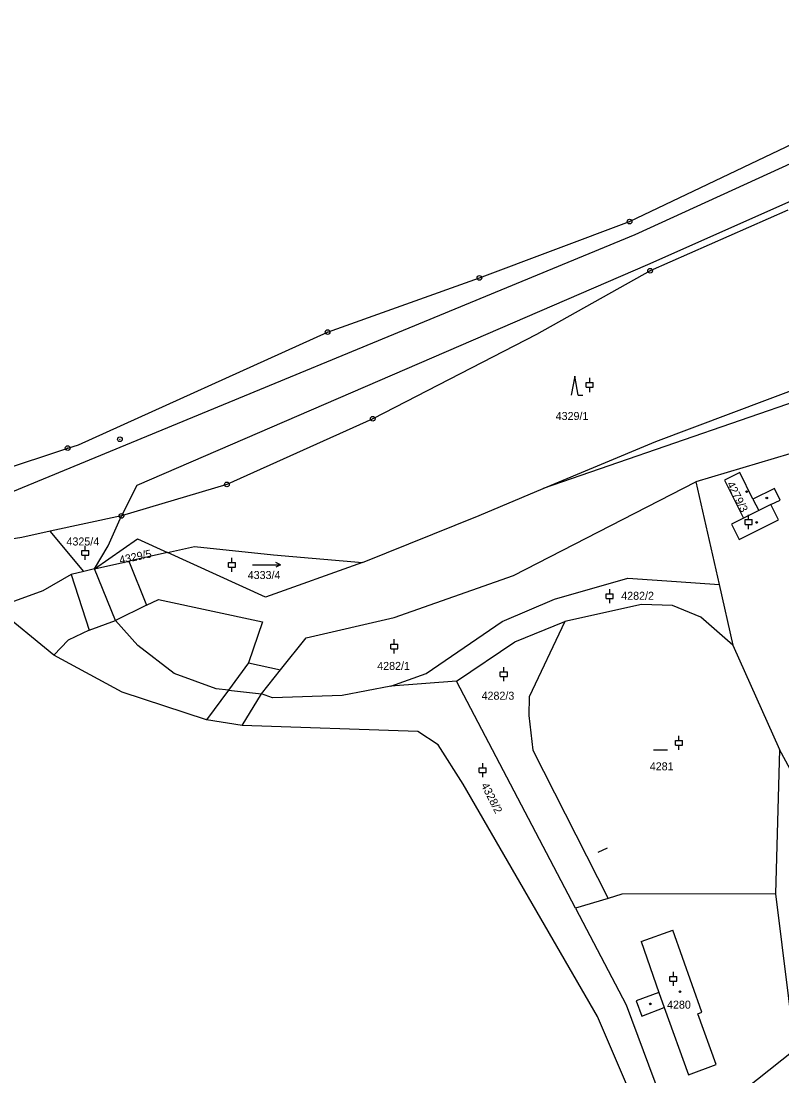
# Model space of a CAD drawing. Extents: x -733394 to -722299, y -1082822 to -1075049.
# Drawn here: x -730959.3 to -730797.5, y -1079150.5 to -1078926.3 of the extents above; entities that cross this region are included whole.
import ezdxf

# ---------------------------------------------------------------- set-up
doc = ezdxf.new("R2010")
doc.units = 0
for name, color, linetype in [('Hranice parcel', 7, 'Continuous'), ('Parcelní čísla', 7, 'Continuous'), ('Vnitřní kresba', 7, 'Continuous'), ('Značky bodu BP', 7, 'Continuous'), ('Značky budov', 7, 'Continuous'), ('Značky kultur', 7, 'Continuous')]:
    doc.layers.add(name, color=color, linetype=linetype)

msp = doc.modelspace()

# ---------------------------------------------------------------- linework, layer by layer
at = {"layer": 'Hranice parcel'}
for p, q in [((-730758.21, -1078994.58), (-730848.25, -1079025.68)), ((-730815.79, -1079024.26), (-730810.86, -1079046.05)), ((-730937.95, -1079031.48), (-730953.08, -1079034.76)), ((-730945.93, -1079043.27), (-730953.08, -1079034.76)), ((-730928.15, -1079039.25), (-730936.34, -1079041.08)), ((-730943.66, -1079042.71), (-730945.93, -1079043.27)), ((-730943.66, -1079042.71), (-730936.34, -1079041.08)), ((-730810.86, -1079046.05), (-730807.95, -1079058.94)), ((-730807.95, -1079058.94), (-730798.03, -1079081.14)), ((-730866.69, -1079066.63), (-730880.7, -1079067.69)), ((-730841.4, -1079114.86), (-730866.69, -1079066.63)), ((-730798.03, -1079081.14), (-730798.88, -1079111.76)), ((-730798.88, -1079111.76), (-730794.74, -1079144.85)), ((-730834.45, -1079112.77), (-730841.4, -1079114.86)), ((-730819.09, -1079164.08), (-730794.74, -1079144.85))]:
    msp.add_line(p, q, dxfattribs=at)
for points in [[(-730987.01, -1079028.33), (-730979.13, -1079026.93), (-730949.37, -1079017.07), (-730947.09, -1079016.4), (-730894.11, -1078992.42), (-730861.84, -1078980.93), (-730829.91, -1078968.95), (-730789, -1078949.44), (-730744.72, -1078928.85), (-730735.03, -1078923.85), (-730722.89, -1078918.38), (-730707.51, -1078912.04)], [(-730796.25, -1078966.53), (-730825.54, -1078979.41), (-730849.68, -1078992.93), (-730884.52, -1079010.85), (-730915.53, -1079024.81), (-730937.95, -1079031.48)], [(-730848.25, -1079025.68), (-730824.32, -1079015.66), (-730792.29, -1079003.64), (-730777.35, -1078991.66), (-730760.34, -1078992.61)], [(-730742.62, -1079005.63), (-730749.62, -1079008.52), (-730753.16, -1079010), (-730767.99, -1079015.09), (-730778.09, -1079014.53), (-730792.49, -1079017.27), (-730815.79, -1079024.26)], [(-730803.73, -1079027.96), (-730806.45, -1079022.27), (-730809.71, -1079023.9), (-730805.68, -1079031.96), (-730808.23, -1079033.23), (-730806.6, -1079036.49), (-730798.25, -1079032.32), (-730799.89, -1079029.03), (-730797.88, -1079028.14), (-730799.12, -1079025.66), (-730803.73, -1079027.96)], [(-730904.1, -1079064.2), (-730898.65, -1079057.37), (-730879.99, -1079053.06), (-730854.58, -1079044.14), (-730815.79, -1079024.26)], [(-730886.71, -1079041.4), (-730861.92, -1079031.4), (-730848.25, -1079025.68)], [(-730943.66, -1079042.71), (-730940.77, -1079037.83), (-730937.95, -1079031.48)], [(-730953.08, -1079034.76), (-730959.14, -1079036.07), (-730969.03, -1079037.66), (-730984.36, -1079040.08), (-730988.05, -1079040.44)], [(-730943.66, -1079042.71), (-730934.49, -1079036.36), (-730928.15, -1079039.25)], [(-730928.15, -1079039.25), (-730922.38, -1079037.96), (-730905.62, -1079039.79), (-730886.71, -1079041.4)], [(-730886.71, -1079041.4), (-730907.29, -1079048.74), (-730928.15, -1079039.25)], [(-730936.34, -1079041.08), (-730932.64, -1079050.47), (-730930.08, -1079049.25), (-730907.92, -1079054.02), (-730910.92, -1079062.73), (-730904.1, -1079064.2)], [(-730945.93, -1079043.27), (-730948.61, -1079043.94), (-730954.65, -1079047.43), (-730964.65, -1079051.01)], [(-730880.7, -1079067.69), (-730873.12, -1079064.97), (-730857.02, -1079053.92), (-730845.88, -1079049.15), (-730830.25, -1079044.72), (-730819.93, -1079045.43), (-730810.86, -1079046.05)], [(-730818.01, -1079184.84), (-730818.76, -1079179.82), (-730836.76, -1079137.87), (-730865.26, -1079088.5), (-730870.59, -1079080.16), (-730874.93, -1079077.28), (-730912.27, -1079075.99), (-730919.86, -1079074.78), (-730937.75, -1079068.97), (-730952.33, -1079061.05), (-730964.65, -1079051.01)], [(-730807.95, -1079058.94), (-730814.74, -1079053.02), (-730820.76, -1079050.51), (-730827.4, -1079050.33), (-730843.65, -1079053.92)], [(-730780.05, -1079050.39), (-730772.67, -1079061.9), (-730784.5, -1079069.05), (-730780.3, -1079075.98), (-730788.63, -1079081.1), (-730790.35, -1079082.13), (-730791.27, -1079080.58), (-730791.98, -1079081), (-730792.65, -1079079.88), (-730794.92, -1079081.23), (-730794.25, -1079082.35), (-730794.94, -1079082.76), (-730794.02, -1079084.31), (-730795.73, -1079085.33), (-730798.03, -1079081.14)], [(-730866.69, -1079066.63), (-730854.32, -1079058.25), (-730843.65, -1079053.92)], [(-730843.65, -1079053.92), (-730851.25, -1079069.96), (-730851.31, -1079073.93), (-730850.45, -1079081.26), (-730834.45, -1079112.77)], [(-730880.7, -1079067.69), (-730891.01, -1079069.66), (-730905.82, -1079070.12), (-730908.16, -1079069.29), (-730904.1, -1079064.2)], [(-730798.88, -1079111.76), (-730831.53, -1079111.89), (-730834.45, -1079112.77)], [(-730841.4, -1079114.86), (-730830.66, -1079135.35), (-730823.42, -1079154.78), (-730819.09, -1079164.08)]]:
    msp.add_lwpolyline(points, dxfattribs=at)
at = {"layer": 'Vnitřní kresba'}
for p, q in [((-730828.75, -1078971.72), (-730789.28, -1078953.63)), ((-730784.77, -1078959.77), (-730826.08, -1078978.11)), ((-730968.57, -1079029.42), (-730828.75, -1078971.72)), ((-730826.08, -1078978.11), (-730934.66, -1079025)), ((-730934.66, -1079025), (-730937.95, -1079031.48)), ((-730803.73, -1079027.96), (-730802.42, -1079030.33)), ((-730799.89, -1079029.03), (-730802.42, -1079030.33)), ((-730802.42, -1079030.33), (-730805.68, -1079031.96)), ((-730939.2, -1079053.7), (-730943.66, -1079042.71)), ((-730948.61, -1079043.94), (-730944.77, -1079055.78)), ((-730932.64, -1079050.47), (-730939.2, -1079053.7)), ((-730944.77, -1079055.78), (-730939.2, -1079053.7)), ((-730934.46, -1079059.02), (-730939.2, -1079053.7)), ((-730944.77, -1079055.78), (-730949.24, -1079057.87)), ((-730949.24, -1079057.87), (-730952.33, -1079061.05)), ((-730926.7, -1079064.98), (-730934.46, -1079059.02)), ((-730910.92, -1079062.73), (-730915.21, -1079068.52)), ((-730917.83, -1079068.23), (-730926.7, -1079064.98)), ((-730915.21, -1079068.52), (-730919.86, -1079074.78)), ((-730915.21, -1079068.52), (-730917.83, -1079068.23)), ((-730915.21, -1079068.52), (-730908.16, -1079069.29)), ((-730912.27, -1079075.99), (-730908.16, -1079069.29)), ((-730836.55, -1079102.96), (-730834.6, -1079102.03)), ((-730827.47, -1079121.93), (-730820.7, -1079119.53)), ((-730814.56, -1079136.94), (-730820.7, -1079119.53)), ((-730827.47, -1079121.93), (-730823.72, -1079132.72)), ((-730823.72, -1079132.72), (-730828.48, -1079134.52)), ((-730828.48, -1079134.52), (-730827.27, -1079137.76)), ((-730823.72, -1079132.72), (-730822.54, -1079135.94)), ((-730827.27, -1079137.76), (-730822.54, -1079135.94)), ((-730822.54, -1079135.94), (-730817.4, -1079150.21)), ((-730815.4, -1079137.26), (-730814.56, -1079136.94)), ((-730811.53, -1079148.06), (-730815.4, -1079137.26)), ((-730817.4, -1079150.21), (-730811.53, -1079148.06))]:
    msp.add_line(p, q, dxfattribs=at)
at = {"layer": 'Značky bodu BP'}
for centre, radius in [((-730829.91, -1078968.95), 0.5), ((-730829.91, -1078968.95), 0.0303), ((-730825.54, -1078979.41), 0.5), ((-730825.54, -1078979.41), 0.0303), ((-730861.84, -1078980.93), 0.5), ((-730861.84, -1078980.93), 0.0303), ((-730894.11, -1078992.42), 0.5), ((-730894.11, -1078992.42), 0.0303), ((-730884.52, -1079010.85), 0.5), ((-730884.52, -1079010.85), 0.0303), ((-730938.27, -1079015.21), 0.5), ((-730938.27, -1079015.21), 0.0303), ((-730949.37, -1079017.07), 0.5), ((-730949.37, -1079017.07), 0.0303), ((-730915.53, -1079024.81), 0.5), ((-730915.53, -1079024.81), 0.0303), ((-730937.95, -1079031.48), 0.5), ((-730937.95, -1079031.48), 0.0303)]:
    msp.add_circle(centre, radius, dxfattribs=at)
at = {"layer": 'Značky budov'}
for centre in [(-730805.03, -1079026.32), (-730800.73, -1079027.68), (-730802.88, -1079032.88), (-730819.19, -1079132.59), (-730825.5, -1079135.17)]:
    msp.add_circle(centre, 0.175, dxfattribs=at)
at = {"layer": 'Značky kultur'}
for p, q in [((-730841.57, -1079001.82), (-730842.32, -1079005.82)), ((-730840.82, -1079005.82), (-730841.57, -1079001.82)), ((-730838.37, -1079003.16), (-730838.37, -1079002.16)), ((-730839.12, -1079003.16), (-730837.62, -1079003.16)), ((-730839.12, -1079004.16), (-730839.12, -1079003.16)), ((-730839.12, -1079004.16), (-730837.62, -1079004.16)), ((-730838.37, -1079005.16), (-730838.37, -1079004.16)), ((-730837.62, -1079004.16), (-730837.62, -1079003.16)), ((-730840.82, -1079005.82), (-730839.82, -1079005.82)), ((-730804.61, -1079032.28), (-730804.61, -1079031.28)), ((-730805.36, -1079032.28), (-730803.86, -1079032.28)), ((-730805.36, -1079033.28), (-730805.36, -1079032.28)), ((-730805.36, -1079033.28), (-730803.86, -1079033.28)), ((-730804.61, -1079034.28), (-730804.61, -1079033.28)), ((-730803.86, -1079033.28), (-730803.86, -1079032.28)), ((-730945.62, -1079038.85), (-730945.62, -1079037.85)), ((-730946.37, -1079038.85), (-730944.87, -1079038.85)), ((-730946.37, -1079039.85), (-730946.37, -1079038.85)), ((-730946.37, -1079039.85), (-730944.87, -1079039.85)), ((-730945.62, -1079040.85), (-730945.62, -1079039.85)), ((-730944.87, -1079039.85), (-730944.87, -1079038.85)), ((-730914.46, -1079041.37), (-730914.46, -1079040.37)), ((-730915.21, -1079041.37), (-730913.71, -1079041.37)), ((-730915.21, -1079042.37), (-730915.21, -1079041.37)), ((-730915.21, -1079042.37), (-730913.71, -1079042.37)), ((-730914.46, -1079043.37), (-730914.46, -1079042.37)), ((-730913.71, -1079042.37), (-730913.71, -1079041.37)), ((-730910.1, -1079041.86), (-730904.1, -1079041.86)), ((-730904.1, -1079041.86), (-730905.08, -1079041.36)), ((-730904.1, -1079041.86), (-730905.08, -1079042.36)), ((-730834.13, -1079048.05), (-730834.13, -1079047.05)), ((-730834.88, -1079048.05), (-730833.38, -1079048.05)), ((-730834.88, -1079049.05), (-730834.88, -1079048.05)), ((-730834.88, -1079049.05), (-730833.38, -1079049.05)), ((-730834.13, -1079050.05), (-730834.13, -1079049.05)), ((-730833.38, -1079049.05), (-730833.38, -1079048.05)), ((-730879.93, -1079058.71), (-730879.93, -1079057.71)), ((-730880.68, -1079058.71), (-730879.18, -1079058.71)), ((-730880.68, -1079059.71), (-730880.68, -1079058.71)), ((-730880.68, -1079059.71), (-730879.18, -1079059.71)), ((-730879.93, -1079060.71), (-730879.93, -1079059.71)), ((-730879.18, -1079059.71), (-730879.18, -1079058.71)), ((-730857.39, -1079064.61), (-730855.89, -1079064.61)), ((-730857.39, -1079065.61), (-730857.39, -1079064.61)), ((-730856.64, -1079064.61), (-730856.64, -1079063.61)), ((-730855.89, -1079065.61), (-730855.89, -1079064.61)), ((-730857.39, -1079065.61), (-730855.89, -1079065.61)), ((-730856.64, -1079066.61), (-730856.64, -1079065.61)), ((-730819.4, -1079079.19), (-730819.4, -1079078.19)), ((-730820.15, -1079079.19), (-730818.65, -1079079.19)), ((-730820.15, -1079080.19), (-730820.15, -1079079.19)), ((-730820.15, -1079080.19), (-730818.65, -1079080.19)), ((-730819.4, -1079081.19), (-730819.4, -1079080.19)), ((-730818.65, -1079080.19), (-730818.65, -1079079.19)), ((-730824.83, -1079081.19), (-730821.83, -1079081.19)), ((-730861.89, -1079085.03), (-730860.39, -1079085.03)), ((-730861.89, -1079086.03), (-730861.89, -1079085.03)), ((-730861.14, -1079085.03), (-730861.14, -1079084.03)), ((-730860.39, -1079086.03), (-730860.39, -1079085.03)), ((-730861.89, -1079086.03), (-730860.39, -1079086.03)), ((-730861.14, -1079087.03), (-730861.14, -1079086.03)), ((-730821.33, -1079129.34), (-730819.83, -1079129.34)), ((-730821.33, -1079130.34), (-730821.33, -1079129.34)), ((-730821.33, -1079130.34), (-730819.83, -1079130.34)), ((-730820.58, -1079129.34), (-730820.58, -1079128.34)), ((-730820.58, -1079131.34), (-730820.58, -1079130.34)), ((-730819.83, -1079130.34), (-730819.83, -1079129.34))]:
    msp.add_line(p, q, dxfattribs=at)

# ---------------------------------------------------------------- texts
at = {"layer": 'Parcelní čísla'}
for s, p in [('4329/1', (-730845.62, -1079011.11)), ('4325/4', (-730949.62, -1079037.77)), ('4333/4', (-730911.09, -1079044.9)), ('4282/2', (-730831.68, -1079049.31)), ('4282/1', (-730883.56, -1079064.21)), ('4282/3', (-730861.37, -1079070.54)), ('4281', (-730825.61, -1079085.55)), ('4280', (-730821.94, -1079136.19))]:
    msp.add_text(s, height=1.7, dxfattribs=at).set_placement(p)
for s, rotation, p in [('4279/3', 297, (-730809.31, -1079024.7)), ('4329/5', 12, (-730938.21, -1079041.72)), ('4328/2', 297, (-730861.54, -1079088.71))]:
    msp.add_text(s, height=1.7, rotation=rotation, dxfattribs=at).set_placement(p)

doc.saveas('drawing.dxf')
